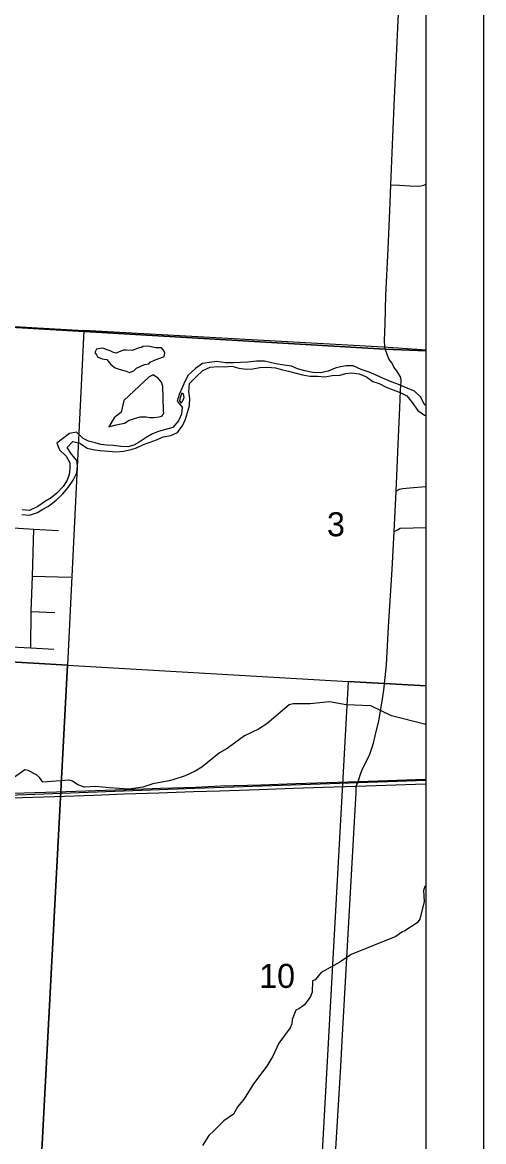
# Model space of a CAD drawing. Extents: x 0 to 34, y 0 to 22.
# Drawn here: x 8.197 to 9, y 16.702 to 18.654 of the extents above; entities that cross this region are included whole.
import ezdxf

# ---------------------------------------------------------------- set-up
doc = ezdxf.new("R2010")
doc.units = 0
for name, color, linetype in [('GM_X_Corporation', 7, 'Continuous'), ('GM_X_County_Road', 7, 'Continuous'), ('GM_X_Major_River', 7, 'Continuous'), ('GM_X_Minor_Lake', 7, 'Continuous'), ('GM_X_Minor_River', 7, 'Continuous'), ('GM_X_Rail_Line', 7, 'Continuous'), ('GM_X_Section', 7, 'Continuous'), ('GM_X_Section_Text', 7, 'Continuous'), ('GM_X_Township_Road', 7, 'Continuous'), ('GM_X_Unincorporated_Text', 7, 'Continuous'), ('GM_X_US_Route', 7, 'Continuous'), ('SH_Cut_Line', 7, 'Continuous'), ('SH_Data', 7, 'Continuous')]:
    doc.layers.add(name, color=color, linetype=linetype)

msp = doc.modelspace()

# ---------------------------------------------------------------- linework, layer by layer
at = {"layer": 'GM_X_Corporation'}
msp.add_lwpolyline([(8.9, 18.0808), (8.9, 20.9), (6.4385, 20.9), (6.4325, 20.8009), (6.4277, 20.7531), (6.4097, 20.4361), (6.4016, 20.3608), (6.4001, 20.2844), (6.3927, 20.2003), (6.389, 20.1539), (6.3883, 20.1254), (6.385, 20.0884), (6.3621, 19.6044), (6.3556, 19.5188), (6.3374, 19.2897), (6.3253, 19.1073), (6.2646, 18.2231), (6.7672, 18.2007), (7.0679, 18.1923), (7.755, 18.1483), (7.8208, 18.1434), (8.8282, 18.0842)], close=True, dxfattribs=at)
msp.add_lwpolyline([(6.624, 15.6351), (6.838, 15.6206), (7.6503, 15.5653), (8.6741, 15.4976), (8.9, 15.4827), (8.9, 18.0808), (8.8282, 18.0842), (7.8208, 18.1434), (7.755, 18.1483), (7.0679, 18.1923), (6.7672, 18.2007)], dxfattribs=at)
at = {"layer": 'GM_X_County_Road'}
for points in [[(8.8284, 18.0837), (8.8279, 18.0888), (8.8276, 18.0991), (8.8284, 18.128), (8.83, 18.1784), (8.8337, 18.2584), (8.8374, 18.3394), (8.8384, 18.3704), (8.8422, 18.4542), (8.8449, 18.5222), (8.8477, 18.5822), (8.8498, 18.62), (8.8543, 18.719), (8.8574, 18.775), (8.8603, 18.8346), (8.8624, 18.8771), (8.8657, 18.976), (8.8694, 19.0681), (8.8705, 19.0855), (8.8812, 19.3221), (8.8852, 19.4112), (8.8858, 19.4182), (8.8984, 19.6699), (8.9, 19.6963)], [(8.7782, 17.3222), (8.7815, 17.3302), (8.7862, 17.3446), (8.7884, 17.3506), (8.7908, 17.3556), (8.7955, 17.3646), (8.8017, 17.378), (8.8082, 17.3971), (8.8115, 17.4098), (8.8174, 17.4359), (8.8235, 17.47), (8.8264, 17.4892), (8.8307, 17.5338), (8.8345, 17.6), (8.841, 17.6997), (8.8442, 17.7661), (8.8478, 17.8362), (8.852, 17.9311), (8.8542, 17.9815), (8.8556, 18.0119), (8.8561, 18.0214), (8.8564, 18.0268), (8.8564, 18.0304), (8.8552, 18.0358), (8.8525, 18.0403), (8.8488, 18.0462), (8.844, 18.0529), (8.8406, 18.0596), (8.8358, 18.0662), (8.8323, 18.0746), (8.8301, 18.0797), (8.8284, 18.0837)], [(8.6744, 15.4971), (8.6792, 15.5612), (8.6825, 15.6215), (8.6875, 15.714), (8.6897, 15.7521), (8.6958, 15.8509), (8.6996, 15.9173), (8.7039, 16.0007), (8.7092, 16.0954), (8.7136, 16.1658), (8.7187, 16.2571), (8.7239, 16.3435), (8.7265, 16.393), (8.7273, 16.4038), (8.73, 16.4485), (8.7313, 16.4698), (8.7324, 16.4898), (8.7335, 16.5104), (8.7388, 16.6231), (8.7513, 16.8335), (8.7536, 16.8781), (8.7747, 17.2502), (8.7783, 17.3106), (8.7782, 17.3222)]]:
    msp.add_lwpolyline(points, dxfattribs=at)
at = {"layer": 'GM_X_Major_River'}
for points in [[(8.1962, 17.7956), (8.2095, 17.7947), (8.2231, 17.7992), (8.2326, 17.8052), (8.2422, 17.81), (8.2555, 17.8209), (8.2673, 17.8318), (8.2769, 17.8428), (8.2853, 17.8556), (8.2918, 17.8684), (8.2931, 17.8806), (8.2916, 17.8901), (8.2822, 17.9008), (8.2751, 17.9126), (8.2847, 17.9228), (8.2972, 17.92), (8.3096, 17.9116), (8.3224, 17.9084), (8.3323, 17.9076), (8.3467, 17.906), (8.3599, 17.9051), (8.3728, 17.9061), (8.3864, 17.9091), (8.3959, 17.9117), (8.4081, 17.918), (8.4176, 17.9214), (8.4305, 17.9262), (8.4423, 17.931), (8.4552, 17.9332), (8.4673, 17.9388), (8.4762, 17.9516), (8.4812, 17.9619), (8.4847, 17.9736), (8.4882, 17.9857), (8.4886, 17.9978), (8.4868, 18.0104), (8.4877, 18.024), (8.4992, 18.0353), (8.511, 18.0466), (8.5239, 18.0526), (8.5372, 18.0536), (8.5493, 18.0531), (8.5614, 18.0542)], [(8.5228, 18.0609), (8.5103, 18.0588), (8.4981, 18.0501), (8.4855, 18.0388), (8.479, 18.0264), (8.4751, 18.0165), (8.4698, 18.0052), (8.4663, 17.9931), (8.4749, 17.9831), (8.474, 17.9706), (8.4686, 17.9589), (8.4587, 17.9476), (8.4462, 17.9439), (8.4337, 17.9402), (8.4234, 17.9365), (8.4127, 17.9297), (8.4002, 17.9219), (8.3907, 17.9166), (8.3808, 17.9137), (8.3683, 17.9142), (8.3558, 17.9158), (8.3437, 17.9166), (8.3335, 17.9178), (8.3237, 17.9206), (8.3123, 17.9233), (8.3025, 17.9283), (8.2913, 17.9394), (8.2791, 17.9372), (8.2669, 17.9274), (8.257, 17.9199), (8.2615, 17.9085), (8.2731, 17.8974), (8.2795, 17.8856), (8.2794, 17.8758), (8.2782, 17.8655), (8.2751, 17.8557), (8.2682, 17.8443), (8.2567, 17.8331), (8.2468, 17.8248), (8.2373, 17.8192), (8.224, 17.8094), (8.2095, 17.8027), (8.1963, 17.8039)], [(8.9, 17.985), (8.8968, 17.9879), (8.8908, 18.0005), (8.8796, 18.0108), (8.8667, 18.0162), (8.8535, 18.0216), (8.841, 18.0263), (8.8267, 18.0321), (8.8131, 18.0386), (8.8007, 18.044), (8.7871, 18.0483), (8.7731, 18.0552), (8.7606, 18.0549), (8.7511, 18.0531), (8.7416, 18.0509), (8.7295, 18.0457), (8.7162, 18.0428), (8.7026, 18.0436), (8.689, 18.046), (8.6757, 18.0495), (8.6655, 18.0542), (8.6527, 18.0561), (8.6383, 18.0582), (8.6281, 18.0609), (8.6183, 18.0632), (8.6046, 18.0633), (8.5895, 18.0616), (8.5766, 18.0609), (8.5641, 18.0602), (8.5505, 18.0603), (8.5353, 18.0627), (8.5228, 18.0609)], [(8.5614, 18.0542), (8.5739, 18.0511), (8.5867, 18.0491), (8.5981, 18.0497), (8.6102, 18.0519), (8.6239, 18.0526), (8.6375, 18.0513), (8.6496, 18.0478), (8.6602, 18.0455), (8.6734, 18.042), (8.6844, 18.0392), (8.6972, 18.0372), (8.7109, 18.0367), (8.7233, 18.0355), (8.7362, 18.0381), (8.7503, 18.0387), (8.7601, 18.0413), (8.77, 18.0427), (8.7832, 18.0407), (8.7961, 18.0357), (8.8074, 18.0276), (8.8179, 18.0242), (8.8304, 18.0176), (8.8425, 18.013), (8.8545, 18.0087), (8.8666, 18.0029), (8.8756, 17.9911), (8.8857, 17.9773), (8.897, 17.9689), (8.9, 17.968)], [(8.4748, 18.007), (8.4718, 17.9999), (8.4703, 17.9938), (8.4733, 17.9898)], [(8.4733, 17.9898), (8.4763, 17.9938), (8.4788, 17.9999), (8.4773, 18.006), (8.4748, 18.007)]]:
    msp.add_lwpolyline(points, dxfattribs=at)
at = {"layer": 'GM_X_Minor_Lake'}
for points in [[(8.3258, 18.0842), (8.3231, 18.0781), (8.3257, 18.0739), (8.3276, 18.0709), (8.3359, 18.0671), (8.3439, 18.0659), (8.3507, 18.0575), (8.3586, 18.0515), (8.3673, 18.0484), (8.3779, 18.0457), (8.3836, 18.0434), (8.3908, 18.0461), (8.3957, 18.0506), (8.4098, 18.057), (8.417, 18.0585), (8.4192, 18.0616), (8.4268, 18.0646), (8.4344, 18.068), (8.4427, 18.0706)], [(8.4427, 18.0706), (8.4439, 18.071), (8.445, 18.0771), (8.4428, 18.082), (8.439, 18.0866), (8.4333, 18.0866), (8.4291, 18.0866), (8.4155, 18.0893), (8.4068, 18.0885), (8.4041, 18.0867), (8.4004, 18.0863), (8.3882, 18.0814), (8.3776, 18.0825), (8.3727, 18.0825), (8.3594, 18.0773), (8.3557, 18.078), (8.35, 18.0811), (8.3364, 18.0857), (8.3258, 18.0842)], [(8.3603, 17.952), (8.3747, 17.955), (8.3831, 17.9603), (8.402, 17.966), (8.4122, 17.9659), (8.419, 17.9648), (8.4255, 17.9651), (8.4349, 17.9659), (8.4395, 17.967), (8.4433, 17.9716), (8.4429, 17.9776), (8.4415, 18.019), (8.4389, 18.0262), (8.4336, 18.0335), (8.4287, 18.0365), (8.4245, 18.0392), (8.4177, 18.0358), (8.3737, 17.9945), (8.3691, 17.9744), (8.3569, 17.9645), (8.3474, 17.9486)], [(8.3474, 17.9486), (8.3603, 17.952)]]:
    msp.add_lwpolyline(points, dxfattribs=at)
at = {"layer": 'GM_X_Minor_River'}
for points in [[(8.9, 17.43), (8.8974, 17.43), (8.8398, 17.4446), (8.8035, 17.4621), (8.7607, 17.4637), (8.7316, 17.4691), (8.6983, 17.4658), (8.6683, 17.4658), (8.6615, 17.464), (8.6228, 17.4306), (8.608, 17.4216), (8.5834, 17.4099), (8.5534, 17.3875), (8.5402, 17.38), (8.5091, 17.3554), (8.4977, 17.3482), (8.4806, 17.3402), (8.4587, 17.3331), (8.4526, 17.3316), (8.4242, 17.3259), (8.4064, 17.3203), (8.3821, 17.3166), (8.3484, 17.3193), (8.3242, 17.3216), (8.3049, 17.3201), (8.2935, 17.3243), (8.2841, 17.3308), (8.2784, 17.3327), (8.2326, 17.329), (8.2265, 17.337), (8.2216, 17.342), (8.2069, 17.3496), (8.2012, 17.3504), (8.1834, 17.3379)], [(8.9, 17.1479), (8.8975, 17.1472), (8.8956, 17.1404), (8.8967, 17.1207), (8.8891, 17.0899), (8.8845, 17.0839), (8.8629, 17.0699), (8.8576, 17.0676), (8.8474, 17.0597), (8.7697, 17.0287), (8.7496, 17.0151), (8.717, 16.9969), (8.7067, 16.9844), (8.7018, 16.9825), (8.7014, 16.9628), (8.6987, 16.9552), (8.6881, 16.9408), (8.6782, 16.9336), (8.6729, 16.9317), (8.6665, 16.9154), (8.6661, 16.9075), (8.6634, 16.9006), (8.6437, 16.8737), (8.633, 16.8514), (8.6224, 16.8339), (8.5996, 16.8032), (8.5829, 16.7771), (8.5719, 16.7638), (8.5646, 16.7501), (8.5479, 16.7384), (8.5301, 16.7214), (8.5214, 16.713), (8.5104, 16.6956)]]:
    msp.add_lwpolyline(points, dxfattribs=at)
at = {"layer": 'GM_X_Rail_Line'}
msp.add_lwpolyline([(2.1, 17.1885), (2.293, 17.1932), (3.2433, 17.211), (3.5049, 17.2168), (5.1641, 17.2441), (5.3961, 17.2441), (6.3843, 17.2591), (6.7484, 17.272), (7.243, 17.2836), (8.0477, 17.3015), (8.4974, 17.3184), (8.9, 17.3324)], dxfattribs=at)
at = {"layer": 'GM_X_Section'}
for points in [[(7.2905, 18.1831), (7.7604, 18.1481), (8.3042, 18.1163), (8.2754, 17.5329), (7.7498, 17.5639), (7.2571, 17.593)], [(7.7498, 17.5639), (8.2754, 17.5329), (8.2225, 16.5336), (7.694, 16.5662)], [(8.2754, 17.5329), (8.7642, 17.5047), (8.7092, 16.506), (8.2225, 16.5336)]]:
    msp.add_lwpolyline(points, close=True, dxfattribs=at)
at = {"layer": 'GM_X_Township_Road'}
for p, q in [((8.8284, 18.0837), (7.821, 18.1428)), ((8.9, 18.0803), (8.8284, 18.0837)), ((8.2146, 17.6883), (8.281, 17.6866)), ((8.2123, 17.6264), (8.2537, 17.6248))]:
    msp.add_line(p, q, dxfattribs=at)
for points in [[(8.8384, 18.3704), (8.8534, 18.3697), (8.8715, 18.3685), (8.8847, 18.368), (8.8908, 18.3685), (8.8958, 18.3701), (8.8998, 18.3719), (8.9, 18.372)], [(8.8478, 17.8362), (8.8531, 17.8401), (8.8589, 17.8409), (8.878, 17.843), (8.9, 17.8445)], [(8.1721, 17.773), (8.2166, 17.7704), (8.2598, 17.7681)], [(8.2114, 17.5632), (8.2123, 17.6264), (8.2146, 17.6883), (8.2166, 17.7704)], [(8.8442, 17.7661), (8.85, 17.769), (8.8549, 17.7718), (8.9, 17.7733)], [(7.9852, 17.6326), (8.0061, 17.6076), (8.026, 17.5866), (8.0336, 17.5802), (8.0388, 17.5766), (8.0449, 17.573), (8.0525, 17.5716), (8.063, 17.5705), (8.0991, 17.5676), (8.1543, 17.5659), (8.2114, 17.5632), (8.2516, 17.561)]]:
    msp.add_lwpolyline(points, dxfattribs=at)
at = {"layer": 'GM_X_Unincorporated_Text'}
for points in [[(8.9, 17.4972), (8.9, 18.0822), (8.8258, 18.0873), (8.3042, 18.1163), (8.2754, 17.5329), (8.7642, 17.5047)], [(8.9, 16.4969), (8.9, 17.4972), (8.7642, 17.5047), (8.7092, 16.506)]]:
    msp.add_lwpolyline(points, close=True, dxfattribs=at)
at = {"layer": 'GM_X_US_Route'}
for points in [[(8.1806, 17.3096), (8.2565, 17.3123), (8.3243, 17.3145), (8.3773, 17.3164), (8.4382, 17.3188), (8.4984, 17.3206), (8.5427, 17.3224), (8.6121, 17.3245), (8.6729, 17.3267), (8.7274, 17.3285), (8.7815, 17.3302), (8.8164, 17.3314), (8.8815, 17.3336), (8.9, 17.3343)], [(8.1773, 17.3016), (8.2532, 17.3043), (8.3211, 17.3066), (8.3741, 17.3085), (8.4345, 17.3104), (8.4951, 17.3127), (8.5406, 17.3141), (8.6088, 17.3165), (8.6696, 17.3187), (8.7206, 17.3202), (8.7782, 17.3222), (8.8127, 17.3232), (8.8815, 17.3256), (8.9, 17.3262)]]:
    msp.add_lwpolyline(points, dxfattribs=at)
at = {"layer": 'SH_Cut_Line'}
msp.add_lwpolyline([(8.9, 15.4827), (8.9, 20.9), (2.1, 20.9), (2.1, 15.9442), (2.2903, 15.9292), (2.5827, 15.9132), (2.6921, 15.9056), (2.7799, 15.8989), (2.8362, 15.8952), (3.3132, 15.8609), (3.9945, 15.8088), (4.2803, 15.787), (4.5905, 15.7634), (4.92, 15.7429), (5.0952, 15.7318), (5.9419, 15.6782), (6.1109, 15.6683), (6.4, 15.6498), (6.624, 15.6351), (6.838, 15.6206), (7.6503, 15.5653), (8.6741, 15.4976)], close=True, dxfattribs=at)
at = {"layer": 'SH_Data'}
msp.add_line((9, 21), (9, 14), dxfattribs=at)

# ---------------------------------------------------------------- texts
at = {"layer": 'GM_X_Section_Text'}
for s, height, p in [('3', 0.0419, (8.7273, 17.7578)), ('10', 0.04186, (8.6094, 16.9703))]:
    msp.add_text(s, height=height, rotation=0, dxfattribs=at).set_placement(p)

doc.saveas('drawing.dxf')
